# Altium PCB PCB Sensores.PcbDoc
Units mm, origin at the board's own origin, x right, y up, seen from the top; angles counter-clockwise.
Board outline 33.78 x 56.52 mm, 2 copper layers (Top Layer, Bottom Layer); 8 components, 8 nets, 46 pads, 6 vias.
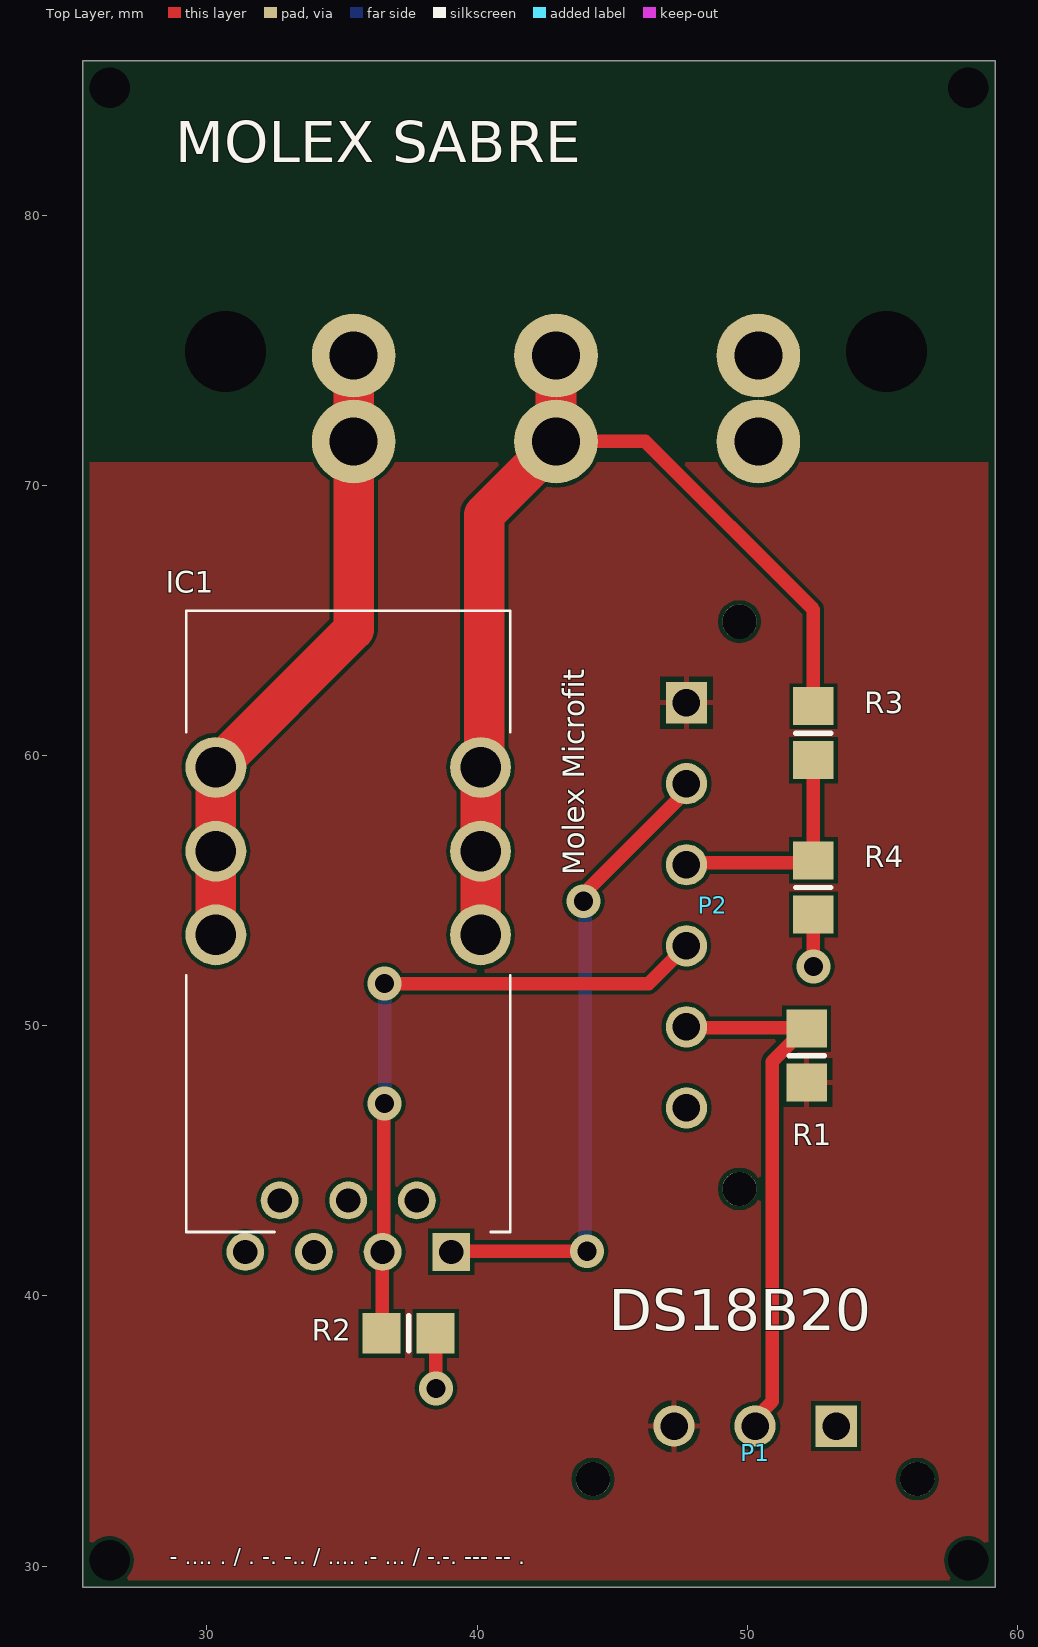
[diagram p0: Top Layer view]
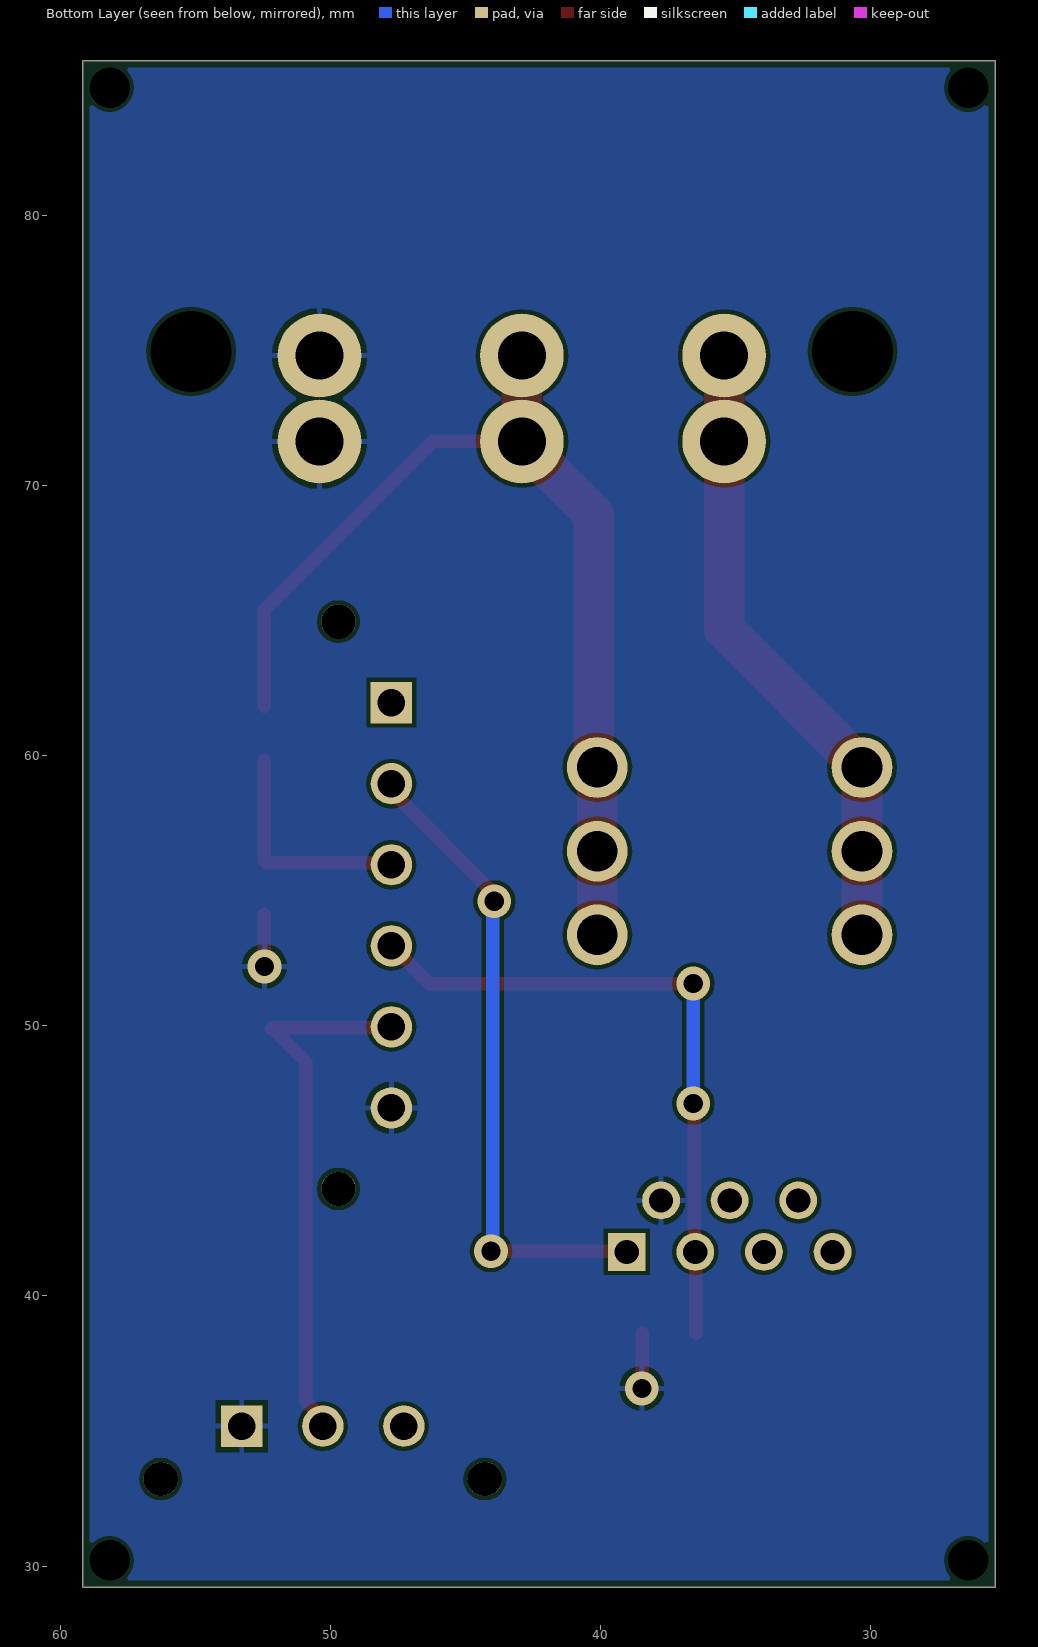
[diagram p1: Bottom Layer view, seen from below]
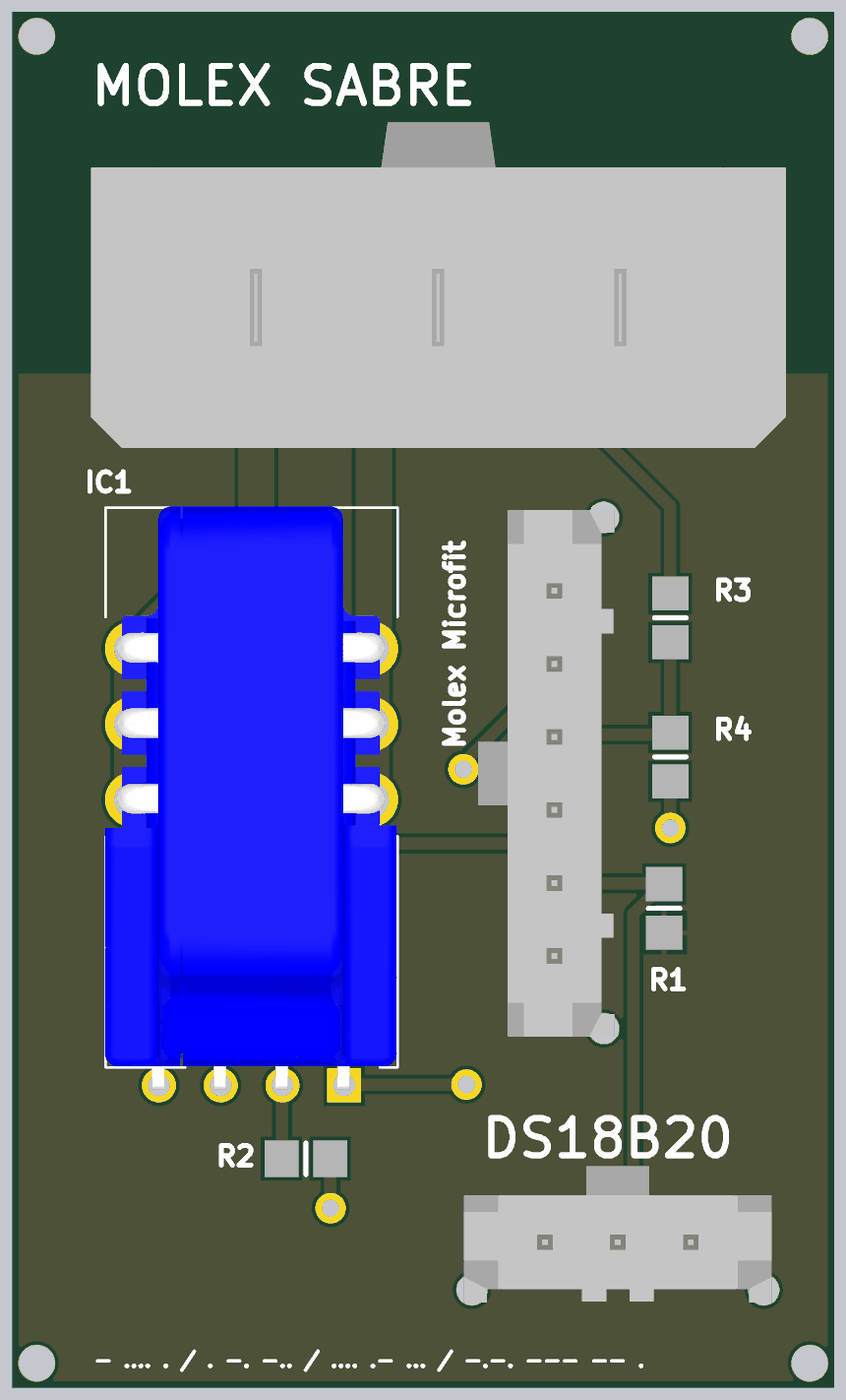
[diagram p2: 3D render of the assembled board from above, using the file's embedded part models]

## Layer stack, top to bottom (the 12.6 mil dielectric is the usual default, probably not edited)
Top Solder: solder mask 0.0102, Solder Resist, Dk 3.5
Top Layer: signal copper 0.0356
Dielectric 1: dielectric 0.32, FR-4, Dk 4.8
Bottom Layer: signal copper 0.0356
Bottom Solder: solder mask 0.0102, Solder Resist, Dk 3.5

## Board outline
25.4,29.21 59.182,29.21 59.182,85.725 25.4,85.725

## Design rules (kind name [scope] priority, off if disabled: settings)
BoardOutlineClearance [All] p1: gap=0.25 ignorepadtopadclearanceinfootprint=FALSE except(0: Arc-SplitContinuation Track-SplitContinuation SMDPad-SplitContinuation THPad-SplitContinuation Via-SplitContinuation Fill-SplitContinuation Poly-SplitContinuation Region-SplitContinuation Text-SplitContinuation)
Clearance Clearance-xPP-xTP-xTT [All] p1: gap=0.15 ignorepadtopadclearanceinfootprint=FALSE except(0: Arc-Hole Track-Hole SMDPad-Hole THPad-Hole Via-Hole Fill-Hole Poly-Hole Region-Hole Text-Hole)
ComponentClearance [All] p1: gap=0.25 collisioncheckmode=3 verticalgap=0.25 showdistances=FALSE
DiffPairsRouting [All] p1: maxlimit=0.25 minlimit=0.25 mostfreqgap=0.25 toplayer_minwidth=0.381 toplayer_maxwidth=0.381 toplayer_prefwidth=0.381 bottomlayer_minwidth=0.381 bottomlayer_maxwidth=0.381 bottomlayer_prefwidth=0.381 maxuncoupledlength=12.5
Height [All] p1: minheight=0 maxheight=25 prefheight=12.5
HoleSize HoleSize-PTH [All] p1: absolutevalues=TRUE maxlimit=2 minlimit=0.25 maxpercent=80.000 minpercent=20.000
HoleToHoleClearance [All] p1: gap=0.35 allowstackedmicrovias=TRUE
MinimumAnnularRing "Minimum IAR  >0.45mm" [((ObjectKind = 'Pad') OR (ObjectKind = 'Via')) And (Layer = 'MultiLayer') And (HoleDiameter > AsMM(0.45))] p1: minimumring=0.175 // minimum inner annular ring for pads > 0.45mm finished hole size
MinimumAnnularRing "Minimum IAR <=0.45mm" [((ObjectKind = 'Pad') OR (ObjectKind = 'Via')) And (Layer = 'MultiLayer') And (HoleDiameter <= AsMM(0.45))] p2: minimumring=0.175 // minimum inner annular ring for pads <= 0.45mm finished hole size
MinimumSolderMaskSliver [All] p1: minsoldermaskwidth=0.08
PlaneClearance PlaneClearance-IPI [All] p1: clearance=0.25
PlaneConnect [All] p1: planeconnectstyle=Relief reliefexpansion=0.175 reliefentries=4 reliefconductorwidth=0.2 reliefairgap=0.2
PolygonConnect PolygonConnect-xTW [All] p1: connectstyle=Relief reliefconductorwidth=0.2 reliefentries=4 polygonreliefangle="90 Angle" airgapwidth=0.2
RoutingCorners [All] p1: cornerstyle=45-Degree minsetback=2.5 maxsetback=2.5
RoutingVias "RoutingVias > 0.45mm" [(ObjectKind = 'Via') And (HoleDiameter > AsMM(0.45))] p1: holewidth=0.5 width=0.85 viastyle="Through Hole" minholewidth=0.5 minwidth=0.85 maxholewidth=0.9 maxwidth=1.25 // finishet hole size > 0.45mm
RoutingVias "RoutingVias <= 0.45mm" [(ObjectKind = 'Via') And (HoleDiameter <= AsMM(0.45))] p2: holewidth=0.3 width=0.65 viastyle="Through Hole" minholewidth=0.25 minwidth=0.6 maxholewidth=0.45 maxwidth=0.8 // finishet hole size <= 0.45mm
SilkToSilkClearance [All] p1: silktosilkclearance=0.2
SilkToSolderMaskClearance SilkscreenOverComponentPads [IsPad] p1: minsilkscreentomaskgap=0.2 clearancetoexposedcopper=TRUE
SolderMaskExpansion [All] p1: expansion=0 istentingtop=FALSE
UnRoutedNet [All] p1: checkbadconnections=TRUE
Width Width-xTW [All] p1: maxlimit=1.5 minlimit=0.15 preferedwidth=0.2
18 further rules are at their usual default settings.

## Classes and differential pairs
component class "PCB Sensores": IC1 "MOLEX SABRE" P1 P2 R1 R2

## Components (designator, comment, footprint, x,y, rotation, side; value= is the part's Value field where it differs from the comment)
IC1 "HO_8-NP_SP33_1000" HO8NPSP33-1000 39.042,41.627 r90 top
"MOLEX SABRE" "PANEL" 43160-4303 57.213,78.983 r180 top
P1 "DS18B20" 43650-0315 50.292,35.179 r0 top
P2 "Molex Microfit" 43650-0615 47.752,54.459 r90 top
R1 "Res2" 6-0805_M 52.197,48.895 r90 top value=4.7K
R2 "Res2" 6-0805_M 37.465,38.608 r180 top value=10K
R3 "Res2" 6-0805_M 52.451,60.833 r90 top value=189K
R4 "Res2" 6-0805_M 52.451,55.118 r90 top value=11K

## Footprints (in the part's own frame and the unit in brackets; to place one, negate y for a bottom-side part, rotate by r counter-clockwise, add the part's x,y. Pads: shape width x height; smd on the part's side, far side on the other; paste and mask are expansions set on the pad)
6-0805_M [mm] "Chip Resistor, Body 2.0x1.2mm, IPC Low Density"
  rect 1.4x1.5 smd: 1(-1,0) 2(1,0)
  silkscreen extent 0,-0.65 0,0.65, body extent -1.07,-0.7 1.07,0.7, height 0.7
43160-4303 [mm] "Molex SABRE 3pin VERTICAL"
  round 3.1 hole 1.78: 1(6.8,7.355) 1(6.8,4.175) 2(14.29,4.175) 2(14.29,7.355) 3(21.78,4.175) 3(21.78,7.355)
  round 1.524 hole 3: 14(2.05,4.025) 14(26.53,4.025)
  body extent 0.01,-2.22 28.59,11.17, height 14.88
43650-0315 [mm]
  rect 1.53x1.53 hole 1.02: 1(3,0)
  round 1.53 hole 1.02: 2(0,0) 3(-3,0)
  round 1.27 hole 1.27: 5(-6,-1.96) 5(6,-1.96)
  body extent -6.32,-2.47 6.33,3.14, height 9.95
43650-0615 [mm]
  rect 1.53x1.53 hole 1.02: 1(7.5,0)
  round 1.53 hole 1.02: 2(4.5,0) 3(1.5,0) 4(-1.5,0) 5(-4.5,0) 6(-7.5,0)
  round 1.27 hole 1.27: 12(-10.5,-1.96) 12(10.5,-1.96)
  body extent -10.84,-2.4 10.8,3.2, height 9.95
HO8NPSP33-1000 [mm]
  rect 1.4x1.4 hole 0.9: 1(0,0)
  round 1.4 hole 0.9: 2(1.905,1.27) 3(0,2.54) 4(1.905,3.81) 5(0,5.08) 6(1.905,6.35) 7(0,7.62)
  round 2.25 hole 1.5: 8(11.736,8.71) 9(14.835,8.71) 10(17.936,8.71) 11(17.936,-1.09) 12(14.836,-1.09) 13(11.736,-1.09)
  silkscreen extent 0.74,-2.19 23.74,9.81, body extent -0.16,-2.16 23.78,9.84, height 11.9

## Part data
IC1: "Integrated Circuit", Manufacturer_Name=LEM, Manufacturer_Part_Number="HO 10-P/SP33"
"MOLEX SABRE": library part "Molex SABRE 3pin vertical", "Molex SABRE 3pin vertical connector"
P1: library part "Header 3", "Header, 3-Pin"
P2: library part "Header 6", "Header, 6-Pin"
R1 R2 R3 R4: "Resistor"

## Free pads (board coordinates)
  round 1 hole 1.5: 2(26.4,30.21) 2(26.4,84.725) 2(58.182,30.21) 2(58.182,84.725)

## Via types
v1: diameter 1.25, hole 0.711, Top Layer to Bottom Layer, 6 vias

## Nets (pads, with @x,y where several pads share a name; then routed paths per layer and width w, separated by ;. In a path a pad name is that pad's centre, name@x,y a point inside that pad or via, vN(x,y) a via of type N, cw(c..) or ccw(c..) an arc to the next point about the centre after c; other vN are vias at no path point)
+3.3: IC1.1 P2.2 | length 24
  Top Layer w0.254: IC1.1 IC1.1@39.071,41.656 ; v1(43.942,54.61) v1@43.942,54.88 ; P2.2@47.752,58.69 P2.2
  Top Layer w0.5: IC1.1@39.071,41.656 v1(44.069,41.656) ; v1@43.942,54.88 P2.2@47.752,58.69
  Bottom Layer w0.254: v1(43.942,54.61) v1@44.005,54.546 ; v1@44.005,41.719 v1(44.069,41.656)
  Bottom Layer w0.5: v1@44.005,41.719 v1@44.005,54.546
+5: P1.3 P2.1 R1.1
Current: IC1.3 P2.4 R2.2 | length 24.8
  Top Layer w0.5: R2.2 36.484,38.627 36.484,41.609 IC1.3 36.539,41.664 36.539,47.08 v1(36.576,47.117) ; v1(36.576,51.562) 46.355,51.562 P2.4
  Bottom Layer w0.5: v1(36.576,47.117) v1(36.576,51.562)
DATA: P1.2 P2.5 R1.2 | length 20
  Top Layer w0.5: P2.5 47.784,49.927 52.165,49.927 R1.2 52.147,49.895 50.927,48.675 50.927,36.093 50.292,35.458 P1.2
GND: "MOLEX SABRE.1" IC1.2 P1.1 P2.6 R2.1 R4.1 | length 4
  Top Layer w0.5: R2.1 38.473,38.6 38.473,36.584 v1(38.481,36.576) ; v1(52.451,52.197) R4.1
NetIC1_8: "MOLEX SABRE.3" IC1.8 IC1.9 IC1.10 | length 23.6
  Top Layer w1.5: IC1.8 IC1.9 IC1.10 35.433,64.664 35.433,71.628 35.433,74.808
V+: "MOLEX SABRE.2" IC1.11 IC1.12 IC1.13 R3.2 | length 38.3
  Top Layer w0.5: 42.923,71.628 46.228,71.628 52.451,65.405 R3.2
  Top Layer w1.5: IC1.13 IC1.12 IC1.11 40.259,59.69 40.259,68.918 42.923,71.582 42.923,71.628 42.923,74.808
Voltage: P2.3 R3.1 R4.2 | length 8.5
  Top Layer w0.5: P2.3 47.831,56.039 52.372,56.039 R4.2 R3.1
pads on no net: "MOLEX SABRE.14" IC1.4 IC1.5 IC1.6 IC1.7 P1.5 P2.12

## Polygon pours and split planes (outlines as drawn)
GND on Bottom Layer "GND" (solid, pour order 0): 23.749,87.122 60.325,87.122 60.325,24.003 60.071,24.257 23.495,24.257
+5 on Top Layer "+5" (solid, pour order 2): 24.257,61.849 24.257,70.866 62.23,70.866 62.23,24.638 62.103,24.511 24.257,24.511

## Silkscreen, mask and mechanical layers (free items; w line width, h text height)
Top Overlay:
  text "- .... . / . -. -.. / .... .- ... / -.-. --- -- ." at 28.632,30.061 h0.6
